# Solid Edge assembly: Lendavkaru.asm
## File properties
Author: jaanm
Template: ansi metric assembly.asm
Last saved by: jaanm
Revision: 16
Application: Solid Edge
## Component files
Kruvi.var1_mir.par
Mootor.var1_mir1.par
Velg.var1_mir1.par
Kruvi.var1.par
Mootor.var1.par
Tyyr.var1.par
Mootor.var1_mir.par
Rehv.var1.par
Velg.var1.par
Anum.var1.psm
Telg.par
Tiib.var1.par
Tiib.var1_mir1.par
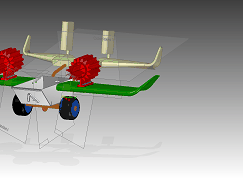
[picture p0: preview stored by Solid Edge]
